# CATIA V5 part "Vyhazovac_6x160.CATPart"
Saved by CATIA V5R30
Part number: Vyhazovac_6x160
Nomenclature: E1710/6x160
Description: MEUSBURGER
Property "Material": "1.221"
Publications: "__DrillHole", "Base"
Bounding box of the stored display mesh (mm): x -5.992 to 5.992, y -5.992 to 5.992, z 0 to 152
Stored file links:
  E:\Bakalarka\Model\Forma_v7\Vyhazovac_6x160.CATPart
  E:\dev\MoldDesign\intel_a\startup\components\MoldCatalog\Ejector\Meusburger\Ejector_E1710\TableE1710.txt
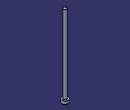
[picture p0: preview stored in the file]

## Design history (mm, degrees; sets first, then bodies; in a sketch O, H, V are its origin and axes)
Parameters
  Ref = "E1710/6x160" {design table}
  D1 = 6 mm {design table}
  D3 = 12 mm {design table}
  L = 160 mm {design table}
  L3 = 5 mm {design table}
  R = 0.5 mm {design table}
  k_d3 = 13 mm {design table}
  k_d1 = 6.2 mm {design table}
  k_F = 0.5 mm {design table}
  kl = 17 mm {design table}
  Mat = "1.221" {design table}
  HeatTreat = "ISO6751" {design table}
  Offset_Parting = 10 mm
  Anti_Rotation = "Normal"
  Anti_Rotation_D = 3.5 mm
  Anti_Rotation_D_Icut = 3.5 mm
  Add_Length_L = 1.8377 mm
  Add_Length_D3 = 0 mm
  SupplierRef = "Meusburger 2017"
  BmpRef = "F_MldEjectorD1"
  DrillHole_Length = 225 mm
  ValidationTest = false
  Anti_Rotation_D_min = 3.5 mm {= OffSet_D1 /2}
  Anti_Rotation_D_max = 5.925 mm {= D3/2-0.075mm}
  Anti_Rotation_D_ref = 3.5 mm {= Anti_Rotation_D}
  Anti_Rotation_D_Icut_ref = 3.5 mm {= Anti_Rotation_D_Icut}
  Anti_Rotation_Ref_Icut = 2.3246 mm
  Offset_L = 20 mm
  D = 6 mm {= D1}
  OffSet_D1 = 7 mm {= D1+2*R}
  OffSet_D3 = 13 mm {= D3+1mm}
  XG_Split = -88 mm
  YG_Split = -31 mm
  ZG_Split = -198 mm
  DirX_Split = 0 mm
  DirY_Split = 0 mm
  DirZ_Split = 1 mm
Set1 "BaseBody"
  Point1 "Base": (0, 0, 0)
  Plane1: type Offset, RefPlane xy-plane, Offset 225 {= DrillHole_Length}, reversed
  Sketch1 "Sketch.2" on xy-plane, origin (0, 0, 0), H (1, 0, 0), V (0, 1, 0)
    point P1 (-0.46, 1.1623)
    point P2 (0.46, 1.1623)
    construction line L1 (-0.46, 1.1623) -> (0.46, 1.1623)
    point P3 (0.46, -1.1623)
    line L2 (0.46, -1.1623) -> (0.46, 1.1623)
    point P4 (-0.46, -1.1623)
    construction line L3 (0.46, -1.1623) -> (-0.46, -1.1623)
    line L4 (-0.46, 1.1623) -> (-0.46, -1.1623)
    point P5 (-0.21, 1.1623)
    arc A1 centre (-0.21, 1.1623) radius 0.25 from (-0.21, 1.4123) to (-0.46, 1.1623) ccw
    point P7 (0.21, 1.1623)
    point P8 (0.21, 1.4123)
    arc A2 centre (0.21, 1.1623) radius 0.25 from (0.46, 1.1623) to (0.21, 1.4123) ccw
    line L5 (-0.21, 1.4123) -> (0.21, 1.4123)
    point P9 (-0.46, -1.1623)
    arc A3 centre (-0.21, -1.1623) radius 0.25 from (-0.46, -1.1623) to (-0.21, -1.4123) ccw
    point P11 (0.21, -1.4123)
    line L6 (-0.21, -1.4123) -> (0.21, -1.4123)
    point P12 (0.46, -1.1623)
    arc A4 centre (0.21, -1.1623) radius 0.25 from (0.21, -1.4123) to (0.46, -1.1623) ccw
    point P14 (-0.46, 1.1623)
    point P15 (-0.46, -1.1623)
    point P16 (0.46, 1.1623)
    point P17 (0.46, -1.1623)
    reference projected circle E1 centre (0, 0) radius 1.25 from edge [face of Shaft1 from Sketch2.L3 | face of Shaft1 from Sketch2.L4]
    reference projected circle E2 centre (0, 0) radius 1.25 from edge [face of Shaft1 from Sketch2.L3 | face of Shaft1 from Sketch2.L4]
    reference projected circle E3 centre (0, 0) radius 1.25 from edge [face of Shaft1 from Sketch2.L3 | face of Shaft1 from Sketch2.L4]
    reference projected circle E4 centre (0, 0) radius 1.25 from edge [face of Shaft1 from Sketch2.L3 | face of Shaft1 from Sketch2.L4]
    point P18 (-0.46, -1.1623)
    point P19 (-0.21, -1.4123)
    point P20 (0.21, -1.4123)
    point P21 (0.46, -1.1623)
    point P22 (-0.21, -1.4123)
    point P23 (0.21, -1.4123)
    distance P14 P15 = 2.3246 (reference)
    distance P16 P17 = 2.3246 (reference)
    distance L1 P14 = 0 (reference)
    radius A1 = 3
    distance L4 V = 3.51
    distance L2 V = 5.935
    distance L5 L6 = 12
    horizontal: L1 H, L3 H, L5 H
    vertical: L2 V, L4 V
    coincidence: P5 L1, P7 L1, P3 P12, P14 L4, P15 L4, P16 L2, P17 L2, P14 E1, P15 E2, P16 E3, P17 E4, P3 P21, P4 P18, P20 P23, P19 P22
    tangency: A1 L4, A2 L2, A2 L5, A1 L5
    symmetry: P1 P9 H, A1 A3 H, P8 P11 H, L5 L6 H, P2 P12 H, A2 A4 H
  DatumSurface1
Body1 "PartBody" (main body)
  Sketch2 "Sketch.1" on zx-plane, origin (0, 0, 0), H (-1, 0, 0), V (0, 0, 1)
    point P1 (0, 160)
    line L1 (3, 160) -> (0, 160)
    line L2 (3, 5) -> (3, 160)
    line L3 (6, 5) -> (3, 5)
    line L4 (6, 0) -> (6, 5)
    point P5 (0, 0)
    line L5 (0, 0) -> (6, 0)
    point P6 (0, 160)
    axis line L6 (0, 160) -> (0, 0)
    point P7 (0, 0)
    point P8 (3, 5)
    point P9 (3, 5)
    line L7 (0, 160) -> (0, 0)
    distance L5 L3 = 5 {= L3}
    distance L5 L1 = 160 {= L}
    distance L2 L6 = 3 {= D1 /2}
    distance L4 L6 = 6 {= D3 /2}
    coincidence: L6 P5, P1 L6, L5 H, L6 V, P7 O, P6 P1, P8 P9
    vertical: L2 V, L7 V
    horizontal: L1 H
  Shaft1 "Shaft.1": profile Sketch2, axis Sketch2.L6, angle 360
  Pocket1 "Pocket.1": profile Sketch1, direction (0, 0, 1), length 6, outer side, deactivated
  Pocket2 "Pocket.2": profile Sketch1, direction (0, 0, 1), length 6, outer side, deactivated
  Fillet1: radius 0.5 {= R}, on edge [face of Shaft1 from Sketch2.L2 | face of Shaft1 from Sketch2.L3]
  Pocket3: profile face of Shaft1 from Sketch2.L1, direction along face of Shaft1 from Sketch2.L1, up to face of DatumSurface1
Body2 "__DrillHole"
  Sketch3 "Sketch.3" on face of Shaft1, origin (0, 0, 0), H (1, 0, 0), V (0, -1, 0)
    point P1 (0, 0)
    reference projected point E1 (0, 0) from Point1
    coincidence: E1 P1
  Hole1 "Hole.1": placed by Sketch3, at (0, 0, 0) direction (0, 0, 1), diameter 7 {= OffSet_D1}, depth 140 {= L-Offset_L}
  Sketch4 "Sketch.4" on face of Shaft1, origin (0, 0, 0), H (1, 0, 0), V (0, -1, 0)
    point P1 (0, 0)
    reference projected point E1 (0, 0) from Point1
    coincidence: E1 P1
  Hole2 "Hole.2": placed by Sketch4, at (0, 0, 0) direction (0, 0, 1), diameter 6 {= D1}, depth 160 {= L}
  Sketch5 "Sketch.5" on face of Shaft1 from Sketch2.L3, origin (0, 0, 5), H (1, 0, 0), V (0, 1, 0)
    point P1 (0, 0)
    reference projected point E1 (0, 0) from Point1
    coincidence: E1 P1
  Hole3 "Hole.3": placed by Sketch5, at (0, 0, 5) direction (0, 0, -1), diameter 13 {= OffSet_D3}, depth 230 {= L3 +DrillHole_Length}
  Chamfer1: length 0.5 {= k_F}, angle 45, on edge [face of Hole1 | face of Hole3]
  Body3 "__Body.1"
    Pocket4 "Pocket.3": profile Sketch1, direction (0, 0, -1), length 225, opposite side length 5, deactivated
  Assemble1: tool Body3
  Chamfer2: length 0.5 {= k_F}, angle 45, on edge [start face of Pocket4 | face of Hole1], deactivated
  Body4 "__Body.2"
    Pocket5 "Pocket.4": profile Sketch1, direction (0, 0, -1), length 225, opposite side length 5, deactivated
  Assemble2: tool Body4
  Chamfer3: length 0.5 {= k_F}, angle 45, on edge [start face of Pocket5 | face of Hole1], deactivated
Relations
  design table "TableE1710", configuration 254, drives Ref, D1, D3, L, L3, R, k_d3, k_d1, k_F, kl, Mat, HeatTreat
  Offset_L = 20mm (deactivated)
  rule "Cut_Head_rule":
    let sketch_cut (length)
    let PartBody_Pocket_Sketch (Boolean)
    let I_PartBody_Pocket (Boolean)
    let D_PartBody_Pocket (Boolean)
    let N_DrillHole_Hole (Boolean)
    let N_DrillHole_Hole_Sketch (Boolean)
    let I_DrillHole_Pocket (Boolean)
    let D_DrillHole_Pocket (Boolean)
    /* --------------------------------------------------------------------------------------*/
    if Anti_Rotation =="Normal"
    {
    	sketch_cut=Anti_Rotation_D_max
    	PartBody_Pocket_Sketch = false
    	I_PartBody_Pocket = false
    	D_PartBody_Pocket = false
    	N_DrillHole_Hole = true
    	N_DrillHole_Hole_Sketch = true
    	I_DrillHole_Pocket = false
    	D_DrillHole_Pocket = false
    	Chamfer1.Activity= true
    	Chamfer2.Activity= false
    	Chamfer3.Activity= false
    }
    if Anti_Rotation == "I_Cut"
    {
    	sketch_cut=Anti_Rotation_D_Icut_ref
    	PartBody_Pocket_Sketch = true
    	I_PartBody_Pocket = true
    	D_PartBody_Pocket = false
    	N_DrillHole_Hole = false
    	N_DrillHole_Hole_Sketch = false
    	I_DrillHole_Pocket = true
    	D_DrillHole_Pocket = false
    	Chamfer1.Activity= false
    	Chamfer2.Activity= true
    	Chamfer3.Activity= false
    }
    if Anti_Rotation =="D_Cut"
    {
    	sketch_cut=Anti_Rotation_D_max
    	PartBody_Pocket_Sketch = true
    	I_PartBody_Pocket = false
    	D_PartBody_Pocket = true
    	N_DrillHole_Hole = false
    	N_DrillHole_Hole_Sketch = false
    	I_DrillHole_Pocket = false
    	D_DrillHole_Pocket = true
    	Chamfer1.Activity= false
    	Chamfer2.Activity= false
    	Chamfer3.Activity= true
    }
    /* --------------------------------------------------------------------------------------*/
    Sketch1.distance(L2 V) = sketch_cut+0.01mm
    Sketch1.distance(L4 V) =Anti_Rotation_D_ref+0.01mm
    Sketch1.radius(A1) =D/2
    Pocket4.FirstLimit.Depth = DrillHole_Length
    Pocket5.FirstLimit.Depth = DrillHole_Length
    Pocket1.FirstLimit.Depth = L3+1mm
    Pocket2.FirstLimit.Depth = L3+1mm
    Pocket4.SecondLimit.Depth = L3
    Pocket5.SecondLimit.Depth =L3
    Pocket1.Activity = I_PartBody_Pocket
    Pocket2.Activity = D_PartBody_Pocket
    Sketch1.Activity =PartBody_Pocket_Sketch
    Hole3.Activity= N_DrillHole_Hole
    Sketch5.Activity = N_DrillHole_Hole_Sketch
    Pocket4.Activity = I_DrillHole_Pocket
    Pocket5.Activity  = D_DrillHole_Pocket
  rule "Anti_Rotation_Icut_constrain":
    let Ref1(length)
    let Ref2(length)
    let Ref3(length)
    let Diam1(length)
    let Diam2(length)
    let Add_Length_Lmin (length)
    Ref1=Sketch1.distance(P14 P15)
    Ref2=Sketch1.distance(P16 P17)
    Diam1=D
    Diam2=D3
    /* --------------------------------------------------------------------*/
    if Ref1 >Ref2
    	Anti_Rotation_Ref_Icut = Ref1
    else
    	Anti_Rotation_Ref_Icut  =Ref2
    Add_Length_D3 .InferiorRange=Anti_Rotation_Ref_Icut /2+Diam1/2 -Diam2/2
    if Add_Length_D3 .InferiorRange<0mm
    	Add_Length_D3 .InferiorRange=0mm
    if ValidationTest == "true"
    	Ref3   = 2*Add_Length_L +Anti_Rotation_Ref_Icut  +2*Diam1/2
    else
    	Ref3  =Diam2+2*Add_Length_D3
    if Ref3 <Diam2
    {
    	Ref3 =Diam2
    }
    /* --------------------------------------------------------------------*/
    Sketch1.distance(L5 L6) = Ref3
    Add_Length_L .InferiorRange=Diam2/2-Anti_Rotation_Ref_Icut/2-Diam1/2
    Add_Length_Lmin=Diam2/2-Anti_Rotation_Ref_Icut/2-Diam1/2
    if Add_Length_Lmin<0mm
    	Add_Length_L .InferiorRange=0mm
    else
    	Add_Length_L .InferiorRange=Add_Length_Lmin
